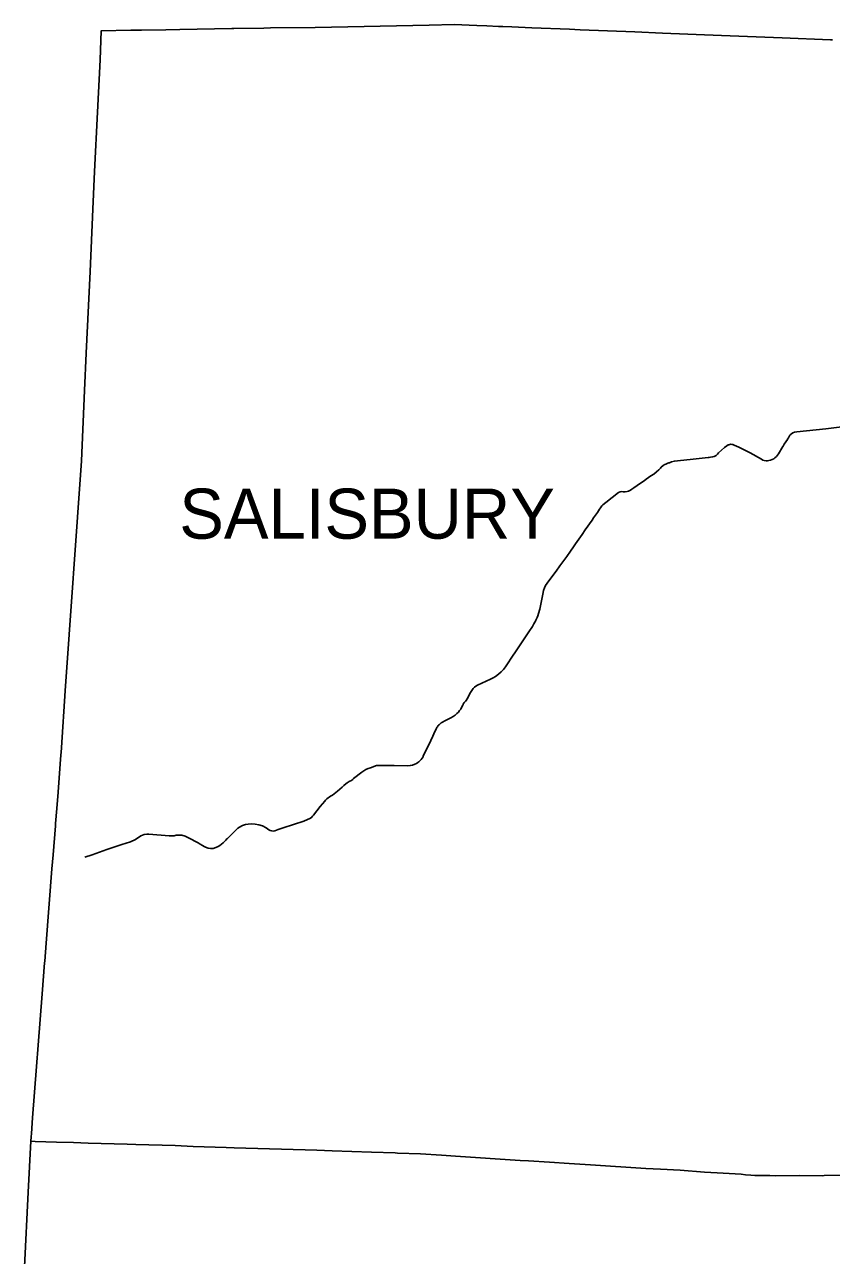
# Model space of a CAD drawing. Extents: x 0 to 2603, y -226 to 830.
# Drawn here: x 60.93 to 82.69, y 673.53 to 706.72 of the extents above; entities that cross this region are included whole.
import ezdxf

# ---------------------------------------------------------------- set-up
doc = ezdxf.new("R2010")
doc.units = 0
for name, color, linetype in [('CT_TSH_Map_Town_Limits', 7, 'Continuous'), ('CT_TSH_Map_Town_Text', 7, 'Continuous'), ('CT_TSH_Map_US_and_State_Routes', 7, 'Continuous')]:
    doc.layers.add(name, color=color, linetype=linetype)

msp = doc.modelspace()

# ---------------------------------------------------------------- linework, layer by layer
at = {"layer": 'CT_TSH_Map_Town_Limits'}
for points in [[(61.098, 676.609), (61.108, 676.725), (61.115, 676.816), (61.147, 677.238), (61.404, 680.587), (61.465, 681.416), (61.472, 681.467), (61.509, 681.952), (61.668, 683.951), (61.697, 684.332), (61.762, 685.112), (61.765, 685.174), (61.798, 685.58), (61.833, 686.02), (61.9, 686.91), (61.924, 687.21), (61.926, 687.229), (62.027, 688.757), (62.469, 694.956), (62.548, 696.852), (62.593, 697.862), (62.696, 700.068), (62.772, 701.749), (62.815, 702.759), (62.898, 704.365), (62.966, 705.773), (62.996, 706.555), (63.798, 706.569), (64.08, 706.568), (64.743, 706.584), (65.118, 706.593), (66.519, 706.613), (66.578, 706.618), (67.384, 706.626), (67.566, 706.631), (68.764, 706.647), (71.841, 706.709), (72.516, 706.722), (73.13, 706.694), (73.401, 706.69), (73.716, 706.675), (73.829, 706.669), (74.073, 706.659), (74.614, 706.637), (75.631, 706.598), (75.912, 706.584), (77.391, 706.526), (78.14, 706.493), (79.728, 706.426), (81.366, 706.363), (82.672, 706.315), (82.722, 706.314)], [(61.098, 676.609), (61.031, 675.236), (60.931, 673.222)], [(61.098, 676.609), (61.212, 676.604), (61.79, 676.586), (62.253, 676.574), (62.643, 676.559), (63.695, 676.528), (63.931, 676.518), (64.988, 676.488), (65.479, 676.469), (66.365, 676.439), (66.587, 676.432), (68.813, 676.364), (69.227, 676.347), (70.287, 676.31), (70.924, 676.293), (70.986, 676.288), (71.606, 676.269), (72.176, 676.228), (72.555, 676.204), (74.298, 676.09), (74.524, 676.078), (75.087, 676.041), (75.617, 676.005), (76.19, 675.968), (77.688, 675.876), (78.086, 675.85), (78.615, 675.823), (79.268, 675.777), (79.613, 675.754), (80.254, 675.716), (80.377, 675.7), (80.517, 675.694), (80.625, 675.685), (80.731, 675.683), (81.035, 675.682), (81.194, 675.678), (81.821, 675.682), (82.46, 675.675), (82.5, 675.681), (83.199, 675.691)]]:
    msp.add_lwpolyline(points, dxfattribs=at)
at = {"layer": 'CT_TSH_Map_US_and_State_Routes'}
for points in [[(82.538, 695.824), (81.756, 695.737), (81.694, 695.728), (81.648, 695.711), (81.613, 695.689)], [(83.048, 695.881), (82.538, 695.824)], [(79.95, 695.4), (79.928, 695.393), (79.907, 695.385), (79.869, 695.362), (79.805, 695.316), (79.725, 695.247), (79.651, 695.17), (79.622, 695.137), (79.581, 695.105), (79.528, 695.077), (79.486, 695.063), (79.429, 695.052), (79.392, 695.049), (79.367, 695.049), (79.127, 695.024), (78.881, 694.997), (78.623, 694.969), (78.538, 694.96), (78.457, 694.949), (78.379, 694.929), (78.322, 694.908), (78.305, 694.903), (78.282, 694.894), (78.246, 694.881), (78.182, 694.846)], [(80.067, 695.384), (80.031, 695.397), (80.008, 695.402), (79.975, 695.403), (79.95, 695.4)], [(81.613, 695.689), (81.599, 695.676), (81.586, 695.663), (81.571, 695.646), (81.553, 695.617), (81.532, 695.582), (81.506, 695.543), (81.504, 695.537), (81.421, 695.405), (81.39, 695.351), (81.383, 695.347), (81.261, 695.15), (81.207, 695.072), (81.17, 695.039), (81.137, 695.014), (81.052, 694.972), (81.002, 694.963), (80.971, 694.962), (80.935, 694.96), (80.878, 694.968), (80.845, 694.979), (80.807, 695.003)], [(80.192, 695.323), (80.067, 695.384)], [(80.807, 695.003), (80.498, 695.173), (80.192, 695.323)], [(78.182, 694.846), (78.155, 694.828), (78.105, 694.785), (78.084, 694.762), (78.041, 694.718), (77.977, 694.659), (77.899, 694.599), (77.823, 694.55)], [(77.639, 694.421), (77.542, 694.353), (77.452, 694.288), (77.365, 694.227), (77.313, 694.191), (77.274, 694.162), (77.239, 694.144), (77.217, 694.136), (77.182, 694.126), (77.134, 694.122), (77.073, 694.124), (77.03, 694.128), (76.992, 694.122), (76.95, 694.101), (76.606, 693.837)], [(77.693, 694.46), (77.639, 694.421)], [(77.823, 694.55), (77.693, 694.46)], [(76.606, 693.837), (76.528, 693.77), (76.501, 693.74), (76.46, 693.687), (76.44, 693.654), (76.414, 693.613), (76.381, 693.567), (76.275, 693.417)], [(76.275, 693.417), (76.237, 693.361)], [(76.237, 693.361), (76.053, 693.094), (75.971, 692.975)], [(75.971, 692.975), (75.792, 692.717)], [(75.657, 692.524), (75.555, 692.375)], [(75.733, 692.634), (75.657, 692.524)], [(75.792, 692.717), (75.733, 692.634)], [(75.368, 692.123), (75.265, 691.979)], [(75.555, 692.375), (75.368, 692.123)], [(75.094, 691.753), (75.022, 691.657), (74.978, 691.592), (74.95, 691.533), (74.93, 691.458), (74.91, 691.363)], [(75.265, 691.979), (75.094, 691.753)], [(74.91, 691.363), (74.828, 690.955)], [(74.793, 690.84), (74.771, 690.778), (74.753, 690.733), (74.722, 690.662)], [(74.828, 690.955), (74.793, 690.84)], [(74.667, 690.561), (74.626, 690.49), (74.53, 690.343)], [(74.718, 690.655), (74.667, 690.561)], [(74.722, 690.662), (74.718, 690.655)], [(74.405, 690.158), (74.301, 689.999)], [(74.53, 690.343), (74.405, 690.158)], [(74.136, 689.755), (74.126, 689.741)], [(74.301, 689.999), (74.136, 689.755)], [(74.126, 689.741), (73.902, 689.403)], [(73.716, 689.204), (73.633, 689.141), (73.571, 689.105), (73.5, 689.069)], [(73.787, 689.265), (73.716, 689.204)], [(73.848, 689.331), (73.787, 689.265)], [(73.902, 689.403), (73.848, 689.331)], [(73.151, 688.908), (73.103, 688.88), (73.066, 688.851), (73.032, 688.817), (72.992, 688.765), (72.959, 688.712)], [(73.5, 689.069), (73.151, 688.908)], [(72.867, 688.536), (72.84, 688.497), (72.831, 688.485), (72.819, 688.471), (72.817, 688.469), (72.815, 688.468), (72.814, 688.466), (72.798, 688.449), (72.796, 688.446), (72.788, 688.436), (72.781, 688.426), (72.78, 688.425), (72.775, 688.418), (72.771, 688.41), (72.763, 688.397), (72.758, 688.383), (72.751, 688.365), (72.728, 688.32), (72.694, 688.263), (72.663, 688.22), (72.631, 688.181), (72.59, 688.141)], [(72.959, 688.712), (72.867, 688.536)], [(72.59, 688.141), (72.541, 688.099), (72.486, 688.061), (72.423, 688.026), (72.305, 687.964)], [(72.141, 687.868), (72.118, 687.848), (72.098, 687.83), (72.081, 687.81), (72.065, 687.786), (72.053, 687.764), (72.044, 687.747), (72.02, 687.705)], [(72.305, 687.964), (72.167, 687.888), (72.141, 687.868)], [(71.938, 687.528), (71.83, 687.296)], [(71.997, 687.657), (71.938, 687.528)], [(72.02, 687.705), (71.997, 687.657)], [(71.781, 687.198), (71.68, 686.989)], [(71.83, 687.296), (71.781, 687.198)], [(71.502, 686.799), (71.453, 686.774), (71.389, 686.752), (71.332, 686.739), (71.259, 686.736), (70.901, 686.74)], [(71.68, 686.989), (71.677, 686.974), (71.655, 686.94), (71.629, 686.906), (71.602, 686.876), (71.583, 686.858), (71.564, 686.843), (71.536, 686.821), (71.502, 686.799)], [(70.027, 686.557), (69.803, 686.388), (69.797, 686.382), (69.788, 686.374), (69.782, 686.366), (69.757, 686.347), (69.727, 686.328), (69.707, 686.318), (69.682, 686.306), (69.632, 686.277), (69.594, 686.247), (69.544, 686.201)], [(70.421, 686.738), (70.261, 686.682), (70.199, 686.658), (70.138, 686.63), (70.08, 686.594), (70.027, 686.557)], [(70.512, 686.744), (70.421, 686.738)], [(70.668, 686.743), (70.512, 686.744)], [(70.901, 686.74), (70.668, 686.743)], [(69.435, 686.103), (69.367, 686.045)], [(69.493, 686.155), (69.435, 686.103)], [(69.544, 686.201), (69.493, 686.155)], [(69.086, 685.846), (69.071, 685.834), (69.05, 685.81), (69.027, 685.781), (68.906, 685.631)], [(69.367, 686.045), (69.232, 685.944), (69.185, 685.912), (69.086, 685.846)], [(68.906, 685.631), (68.722, 685.4), (68.7, 685.373), (68.675, 685.345), (68.643, 685.322)], [(67.047, 685.164), (66.961, 685.157), (66.891, 685.147), (66.807, 685.122), (66.726, 685.08), (66.683, 685.049), (66.63, 684.999), (66.569, 684.938)], [(68.463, 685.242), (67.902, 685.056), (67.768, 685.012), (67.677, 684.982), (67.643, 684.974), (67.596, 684.975), (67.552, 684.991), (67.522, 685.009), (67.442, 685.063), (67.343, 685.111), (67.249, 685.142), (67.153, 685.158), (67.047, 685.164)], [(68.643, 685.322), (68.463, 685.242)], [(64.159, 684.881), (64.069, 684.841), (63.922, 684.743), (63.788, 684.681)], [(64.831, 684.841), (64.28, 684.891), (64.223, 684.891), (64.159, 684.881)], [(66.148, 684.555), (66.088, 684.526), (66.02, 684.505), (65.941, 684.506), (65.881, 684.514), (65.808, 684.535), (65.774, 684.553), (65.73, 684.583), (65.664, 684.619), (65.608, 684.651), (65.352, 684.793), (65.264, 684.836), (65.168, 684.859), (65.105, 684.864), (65.019, 684.859), (64.969, 684.845), (64.928, 684.84), (64.831, 684.841)], [(66.569, 684.938), (66.457, 684.827), (66.399, 684.769), (66.397, 684.77), (66.357, 684.728), (66.313, 684.684), (66.282, 684.654), (66.193, 684.584)], [(63.151, 684.471), (62.751, 684.336)], [(63.557, 684.607), (63.151, 684.471)], [(63.788, 684.681), (63.557, 684.607)], [(66.193, 684.584), (66.148, 684.555)], [(62.751, 684.336), (62.553, 684.27)]]:
    msp.add_lwpolyline(points, dxfattribs=at)

# ---------------------------------------------------------------- texts
at = {"layer": 'CT_TSH_Map_Town_Text'}
msp.add_text('SALISBURY', height=1.35, dxfattribs=at).set_placement((65.102, 692.858))

doc.saveas('drawing.dxf')
